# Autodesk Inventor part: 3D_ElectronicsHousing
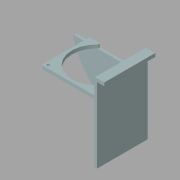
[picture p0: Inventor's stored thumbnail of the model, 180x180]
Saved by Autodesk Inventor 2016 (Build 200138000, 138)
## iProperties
Created: 2016-02
Part Number: 3D_ElectronicsHousing
Material: Generic
Document SubType Name: Modeling
Designer: bongo_000
Density: 1 g/cm^3
Appearance: Default
Title: 3D_ElectronicsHousing.stp
Sending System: SIEMENS PLM Software NX 7.5
Preprocessor: ST-DEVELOPER v11
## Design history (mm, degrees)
feature "Base1"
body "Solid1"
